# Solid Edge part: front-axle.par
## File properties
Author: andyw
Template: iso metric part.par
Last saved by: andyw
Revision: 7
Application: Solid Edge
Accuracy: 0.990
Material Thickness: 1.00 mm
Bend Radius: 1.00 mm
Relief Width: 1.00 mm
Relief Length: 0.00 mm
Neutral Factor: 0.330
Minimum Arc Length: 0.10 mm
Deviational Tolerance: 0.10 mm
Username: andyw
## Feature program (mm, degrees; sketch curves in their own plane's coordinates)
sketch for "ExtrudedProtrusion_1" plane through (0, 0, 0) normal (0, -1, 0) x-axis (1, 0, 0)
  circle centre (0, 0) radius 13
extrude "ExtrudedProtrusion_1" add finite 112 along -normal
sketch for "ExtrudedCutout_1" plane through (0, 0, 0) normal (0, -1, 0) x-axis (1, 0, 0)
  circle centre (0, 0) radius 10
extrude "ExtrudedCutout_1" cut finite 97 along -normal
sketch for "Hole_1" plane through (0, 0, 0) normal (0, -1, 0) x-axis (1, 0, 0)
  hole centre (0, 0) bore radius 4.188
hole "Hole_1" nominal diameter 10 finite
sketch for "Hole_2" plane through (0, 0, 0) normal (0, -1, 0) x-axis (1, 0, 0)
  hole centre (0, 0) bore radius 5
hole "Hole_2" diameter 10 finite
sketch for "Hole_3" plane through (0, 112, 0) normal (0, 1, 0) x-axis (-1, 0, 0)
  hole centre (0, 0) bore radius 6
hole "Hole_3" diameter 12 finite
chamfer "Chamfer_1" setback 2
chamfer "Chamfer_2" setback 1
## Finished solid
Body 1: solid body, 15 faces, 22 edges, 8 vertices.
  Faces by surface: cylinder 6, plane 5, cone 2, spline 2
  Edges by curve: circle 14, intersection 4, spline 4
Bounding box of the edges (mm; curved faces can reach further): 26.000 x 112.000 x 26.000, from (-13, 0, -13) to (13, 112, 13).
Cylindrical faces by radius (mm): R4.188 x1, R4.9999 x1, R5 x1, R6 x1, R10 x1, R13 x1
Conical faces (half-angle, radius in mm at the cone's reference point): 45 deg R10 x1, 45 deg R12 x1
Planar faces by outward normal: +y 2, -y 3
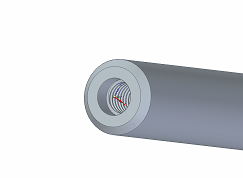
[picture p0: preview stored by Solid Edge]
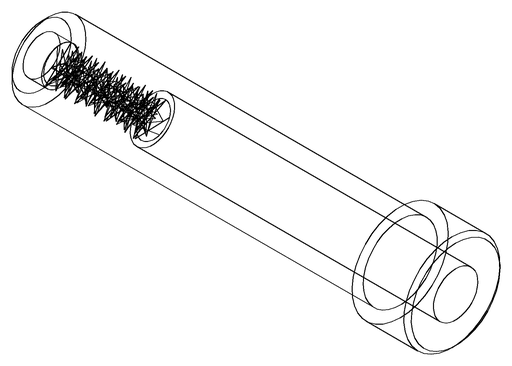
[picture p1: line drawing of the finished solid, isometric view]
